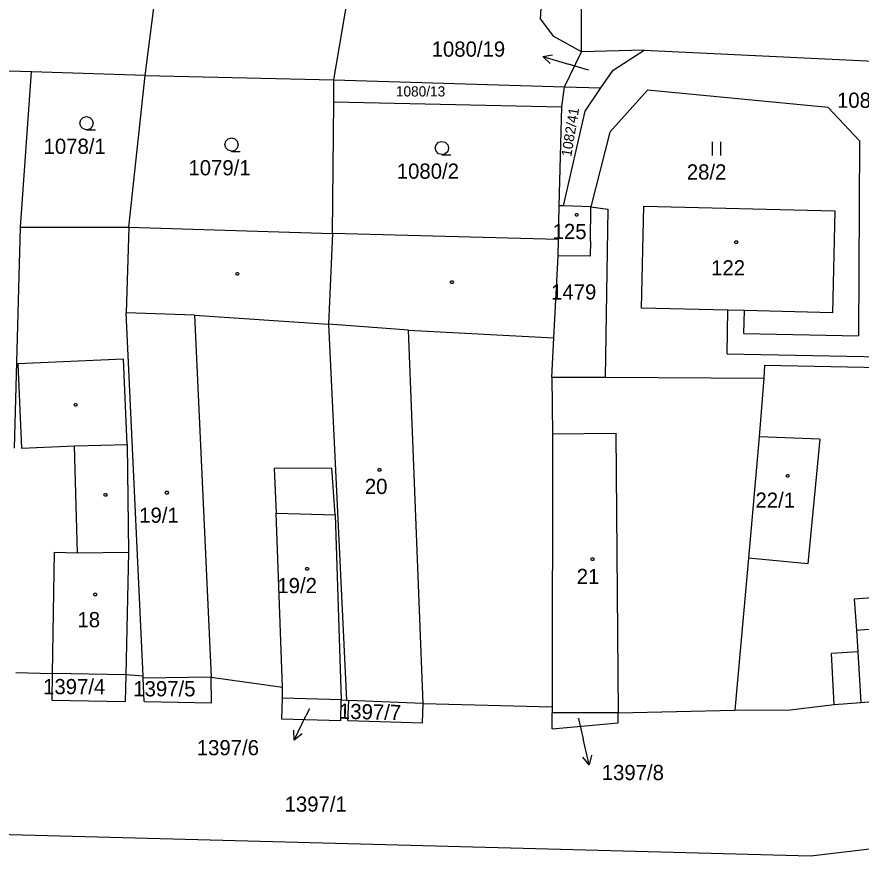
# Model space of a CAD drawing. Extents: x -852001 to -842497, y -1063614 to -1052182.
# Drawn here: x -849494.9 to -849400.5, y -1056341.3 to -1056247.4 of the extents above; entities that cross this region are included whole.
import ezdxf

# ---------------------------------------------------------------- set-up
doc = ezdxf.new("R2010")
doc.units = 0
for name, color, linetype in [('Default', 7, 'Continuous'), ('KN_HRANICE', 7, 'Continuous'), ('KN_KULTURY', 7, 'Continuous'), ('KN_PARCELY', 7, 'Continuous'), ('KN_SLUCKY', 7, 'Continuous')]:
    doc.layers.add(name, color=color, linetype=linetype)

# ---------------------------------------------------------------- blocks, each defined once
blk = doc.blocks.new('304')
at = {"layer": 'Default'}
blk.add_lwpolyline([(0, 0), (-0.38, 0.1), (-0.65, 0.37), (-0.75, 0.74), (-0.65, 1.11), (-0.38, 1.38), (-0.01, 1.48), (0.36, 1.38), (0.63, 1.11), (0.73, 0.73), (0.63, 0.35), (0.36, 0.08), (-0.02, -0.02), (0.98, -0.02)], dxfattribs=at)
blk = doc.blocks.new('306')
at = {"layer": 'Default'}
for p, q in [((-0.5, 1.5), (-0.5, 0)), ((0.5, 0), (0.5, 1.5))]:
    blk.add_line(p, q, dxfattribs=at)
blk = doc.blocks.new('10292')
at = {"layer": 'Default'}
blk.add_line((0, 3), (0, 0), dxfattribs=at)
blk.add_lwpolyline([(-0.5, 2), (0, 3), (0.5, 2)], dxfattribs=at)
blk = doc.blocks.new('402')
at = {"layer": 'Default'}
blk.add_lwpolyline([(0.09, 0.15), (0.18, 0), (0.09, -0.15), (-0.09, -0.15), (-0.18, 0), (-0.09, 0.15), (0.09, 0.15)], dxfattribs=at)

msp = doc.modelspace()

# ---------------------------------------------------------------- linework, layer by layer
at = {"layer": 'KN_HRANICE'}
for p, q in [((-849436.33, -1056247.63), (-849434.92, -1056222.51)), ((-849436.33, -1056247.63), (-849434.92, -1056222.51)), ((-849459.44, -1056254.46), (-849456.85, -1056239.17)), ((-849459.44, -1056254.46), (-849456.85, -1056239.17)), ((-849480.53, -1056253.97), (-849478.74, -1056239.77)), ((-849480.53, -1056253.97), (-849478.74, -1056239.77)), ((-849431.76, -1056251.31), (-849431.74, -1056242.65)), ((-849431.76, -1056251.31), (-849431.74, -1056242.65)), ((-849434.87, -1056249.61), (-849436.33, -1056247.63)), ((-849434.87, -1056249.61), (-849436.33, -1056247.63)), ((-849431.76, -1056251.31), (-849434.87, -1056249.61)), ((-849431.76, -1056251.31), (-849434.87, -1056249.61)), ((-849433.67, -1056255.23), (-849431.76, -1056251.31)), ((-849433.67, -1056255.23), (-849431.76, -1056251.31)), ((-849424.74, -1056251.13), (-849431.76, -1056251.31)), ((-849424.74, -1056251.13), (-849431.76, -1056251.31)), ((-849428.22, -1056253.36), (-849424.74, -1056251.13)), ((-849428.22, -1056253.36), (-849424.74, -1056251.13)), ((-849424.74, -1056251.13), (-849362.03, -1056254.15)), ((-849424.74, -1056251.13), (-849362.03, -1056254.15)), ((-849493.22, -1056253.57), (-849506.8, -1056253.15)), ((-849493.22, -1056253.57), (-849506.8, -1056253.15)), ((-849494.45, -1056270.95), (-849493.22, -1056253.57)), ((-849494.45, -1056270.95), (-849493.22, -1056253.57)), ((-849480.53, -1056253.97), (-849493.22, -1056253.57)), ((-849480.53, -1056253.97), (-849493.22, -1056253.57)), ((-849482.35, -1056270.93), (-849480.53, -1056253.97)), ((-849482.35, -1056270.93), (-849480.53, -1056253.97)), ((-849480.53, -1056253.97), (-849459.44, -1056254.46)), ((-849480.53, -1056253.97), (-849459.44, -1056254.46)), ((-849429.59, -1056255.35), (-849428.22, -1056253.36)), ((-849429.59, -1056255.35), (-849428.22, -1056253.36)), ((-849459.46, -1056256.93), (-849459.44, -1056254.46)), ((-849459.46, -1056256.93), (-849459.44, -1056254.46)), ((-849459.44, -1056254.46), (-849433.67, -1056255.23)), ((-849459.44, -1056254.46), (-849433.67, -1056255.23)), ((-849433.96, -1056257.48), (-849433.67, -1056255.23)), ((-849433.96, -1056257.48), (-849433.67, -1056255.23)), ((-849433.67, -1056255.23), (-849429.59, -1056255.35)), ((-849433.67, -1056255.23), (-849429.59, -1056255.35)), ((-849431.37, -1056257.95), (-849429.59, -1056255.35)), ((-849431.37, -1056257.95), (-849429.59, -1056255.35)), ((-849424.4, -1056255.6), (-849428.61, -1056260.33)), ((-849424.4, -1056255.6), (-849428.61, -1056260.33)), ((-849404.18, -1056257.55), (-849424.4, -1056255.6)), ((-849404.18, -1056257.55), (-849424.4, -1056255.6)), ((-849459.61, -1056271.66), (-849459.46, -1056256.93)), ((-849459.61, -1056271.66), (-849459.46, -1056256.93)), ((-849459.46, -1056256.93), (-849433.96, -1056257.48)), ((-849459.46, -1056256.93), (-849433.96, -1056257.48)), ((-849434.27, -1056268.55), (-849433.96, -1056257.48)), ((-849434.27, -1056268.55), (-849433.96, -1056257.48)), ((-849433.77, -1056268.56), (-849431.37, -1056257.95)), ((-849433.77, -1056268.56), (-849431.37, -1056257.95)), ((-849400.7, -1056261.28), (-849404.18, -1056257.55)), ((-849400.7, -1056261.28), (-849404.18, -1056257.55)), ((-849428.61, -1056260.33), (-849430.72, -1056268.66)), ((-849428.61, -1056260.33), (-849430.72, -1056268.66)), ((-849400.7, -1056261.28), (-849400.81, -1056283.1)), ((-849400.7, -1056261.28), (-849400.81, -1056283.1)), ((-849434.34, -1056272.32), (-849434.27, -1056268.55)), ((-849434.34, -1056272.32), (-849434.27, -1056268.55)), ((-849433.77, -1056268.56), (-849434.27, -1056268.55)), ((-849433.77, -1056268.56), (-849434.27, -1056268.55)), ((-849430.72, -1056268.66), (-849433.77, -1056268.56)), ((-849430.72, -1056268.66), (-849433.77, -1056268.56)), ((-849430.76, -1056272.49), (-849430.72, -1056268.66)), ((-849430.76, -1056272.49), (-849430.72, -1056268.66)), ((-849430.72, -1056268.66), (-849428.8, -1056268.93)), ((-849430.72, -1056268.66), (-849428.8, -1056268.93)), ((-849428.8, -1056268.93), (-849429.11, -1056287.73)), ((-849428.8, -1056268.93), (-849429.11, -1056287.73)), ((-849425.04, -1056279.98), (-849424.78, -1056268.57)), ((-849425.04, -1056279.98), (-849424.78, -1056268.57)), ((-849424.78, -1056268.57), (-849403.43, -1056269.1)), ((-849424.78, -1056268.57), (-849403.43, -1056269.1)), ((-849403.43, -1056269.1), (-849403.71, -1056280.52)), ((-849403.43, -1056269.1), (-849403.71, -1056280.52)), ((-849495.12, -1056295.64), (-849494.45, -1056270.95)), ((-849495.12, -1056295.64), (-849494.45, -1056270.95)), ((-849494.45, -1056270.95), (-849482.35, -1056270.93)), ((-849494.45, -1056270.95), (-849482.35, -1056270.93)), ((-849482.35, -1056270.93), (-849482.67, -1056280.51)), ((-849482.35, -1056270.93), (-849482.67, -1056280.51)), ((-849482.35, -1056270.93), (-849459.61, -1056271.66)), ((-849482.35, -1056270.93), (-849459.61, -1056271.66)), ((-849459.61, -1056271.66), (-849460.03, -1056281.78)), ((-849459.61, -1056271.66), (-849460.03, -1056281.78)), ((-849434.34, -1056272.32), (-849459.61, -1056271.66)), ((-849434.34, -1056272.32), (-849459.61, -1056271.66)), ((-849434.38, -1056274.15), (-849434.34, -1056272.32)), ((-849434.38, -1056274.15), (-849434.34, -1056272.32)), ((-849430.76, -1056272.49), (-849430.78, -1056274.18)), ((-849430.76, -1056272.49), (-849430.78, -1056274.18)), ((-849434.84, -1056283.32), (-849434.38, -1056274.15)), ((-849434.84, -1056283.32), (-849434.38, -1056274.15)), ((-849430.78, -1056274.18), (-849434.38, -1056274.15)), ((-849430.78, -1056274.18), (-849434.38, -1056274.15)), ((-849480.75, -1056321.14), (-849482.67, -1056280.51)), ((-849480.75, -1056321.14), (-849482.67, -1056280.51)), ((-849415.41, -1056280.22), (-849425.04, -1056279.98)), ((-849415.41, -1056280.22), (-849425.04, -1056279.98)), ((-849415.48, -1056285.11), (-849415.41, -1056280.22)), ((-849415.48, -1056285.11), (-849415.41, -1056280.22)), ((-849413.55, -1056280.27), (-849415.41, -1056280.22)), ((-849413.55, -1056280.27), (-849415.41, -1056280.22)), ((-849413.61, -1056282.82), (-849413.55, -1056280.27)), ((-849413.61, -1056282.82), (-849413.55, -1056280.27)), ((-849403.71, -1056280.52), (-849413.55, -1056280.27)), ((-849403.71, -1056280.52), (-849413.55, -1056280.27)), ((-849460.03, -1056281.78), (-849458.02, -1056323.85)), ((-849460.03, -1056281.78), (-849458.02, -1056323.85)), ((-849435.06, -1056287.7), (-849434.84, -1056283.32)), ((-849435.06, -1056287.7), (-849434.84, -1056283.32)), ((-849413.61, -1056282.82), (-849400.81, -1056283.1)), ((-849413.61, -1056282.82), (-849400.81, -1056283.1)), ((-849415.48, -1056285.11), (-849362.36, -1056286.11)), ((-849415.48, -1056285.11), (-849362.36, -1056286.11)), ((-849411.31, -1056286.39), (-849411.38, -1056287.83)), ((-849411.31, -1056286.39), (-849411.38, -1056287.83)), ((-849389.17, -1056286.88), (-849411.31, -1056286.39)), ((-849389.17, -1056286.88), (-849411.31, -1056286.39)), ((-849435.06, -1056287.7), (-849434.99, -1056294.05)), ((-849435.06, -1056287.7), (-849429.11, -1056287.73)), ((-849435.06, -1056287.7), (-849434.99, -1056294.05)), ((-849435.06, -1056287.7), (-849429.11, -1056287.73)), ((-849429.11, -1056287.73), (-849411.38, -1056287.83)), ((-849429.11, -1056287.73), (-849411.38, -1056287.83)), ((-849411.38, -1056287.83), (-849411.89, -1056294.39)), ((-849411.38, -1056287.83), (-849411.89, -1056294.39)), ((-849434.99, -1056294.05), (-849435.03, -1056324.6)), ((-849434.99, -1056294.05), (-849435.03, -1056324.6)), ((-849411.89, -1056294.39), (-849413.11, -1056307.95)), ((-849411.89, -1056294.39), (-849413.11, -1056307.95)), ((-849459.67, -1056297.88), (-849466.12, -1056297.93)), ((-849459.67, -1056297.88), (-849466.12, -1056297.93)), ((-849466.12, -1056297.93), (-849465.89, -1056302.94)), ((-849466.12, -1056297.93), (-849465.89, -1056302.94)), ((-849459.31, -1056303.12), (-849459.67, -1056297.88)), ((-849459.31, -1056303.12), (-849459.67, -1056297.88)), ((-849465.19, -1056322.38), (-849465.89, -1056302.94)), ((-849465.19, -1056322.38), (-849465.89, -1056302.94)), ((-849459.31, -1056303.12), (-849458.61, -1056323.81)), ((-849459.31, -1056303.12), (-849458.61, -1056323.81)), ((-849413.11, -1056307.95), (-849414.63, -1056324.97)), ((-849413.11, -1056307.95), (-849414.63, -1056324.97)), ((-849394.9, -1056312.07), (-849401.27, -1056312.56)), ((-849394.9, -1056312.07), (-849401.27, -1056312.56)), ((-849401.27, -1056312.56), (-849401.01, -1056315.99)), ((-849401.27, -1056312.56), (-849401.01, -1056315.99)), ((-849401.01, -1056315.99), (-849400.86, -1056318.43)), ((-849401.01, -1056315.99), (-849400.86, -1056318.43)), ((-849400.86, -1056318.43), (-849403.83, -1056318.61)), ((-849400.86, -1056318.43), (-849403.83, -1056318.61)), ((-849403.52, -1056324.31), (-849403.83, -1056318.61)), ((-849403.52, -1056324.31), (-849403.83, -1056318.61)), ((-849494.97, -1056320.74), (-849490.92, -1056320.87)), ((-849494.97, -1056320.74), (-849490.92, -1056320.87)), ((-849490.92, -1056320.87), (-849490.97, -1056323.82)), ((-849490.92, -1056320.87), (-849490.97, -1056323.82)), ((-849482.68, -1056320.99), (-849490.92, -1056320.87)), ((-849482.68, -1056320.99), (-849490.92, -1056320.87)), ((-849482.68, -1056320.99), (-849482.75, -1056323.99)), ((-849482.68, -1056320.99), (-849482.75, -1056323.99)), ((-849480.75, -1056321.14), (-849482.68, -1056320.99)), ((-849480.75, -1056321.14), (-849482.68, -1056320.99)), ((-849480.74, -1056321.39), (-849480.75, -1056321.14)), ((-849480.74, -1056321.39), (-849480.75, -1056321.14)), ((-849473.17, -1056321.25), (-849480.74, -1056321.39)), ((-849473.17, -1056321.25), (-849480.74, -1056321.39)), ((-849473.12, -1056324.15), (-849473.17, -1056321.25)), ((-849473.17, -1056321.25), (-849465.19, -1056322.38)), ((-849473.12, -1056324.15), (-849473.17, -1056321.25)), ((-849473.17, -1056321.25), (-849465.19, -1056322.38)), ((-849480.64, -1056323.99), (-849480.74, -1056321.39)), ((-849480.64, -1056323.99), (-849480.74, -1056321.39)), ((-849465.18, -1056323.63), (-849465.19, -1056322.38)), ((-849465.18, -1056323.63), (-849465.19, -1056322.38)), ((-849490.97, -1056323.82), (-849482.75, -1056323.99)), ((-849490.97, -1056323.82), (-849482.75, -1056323.99)), ((-849480.64, -1056323.99), (-849473.12, -1056324.15)), ((-849480.64, -1056323.99), (-849473.12, -1056324.15)), ((-849465.24, -1056325.98), (-849465.18, -1056323.63)), ((-849465.24, -1056325.98), (-849465.18, -1056323.63)), ((-849458.61, -1056323.81), (-849465.18, -1056323.63)), ((-849458.61, -1056323.81), (-849465.18, -1056323.63)), ((-849458.67, -1056326.16), (-849458.61, -1056323.81)), ((-849458.67, -1056326.16), (-849458.61, -1056323.81)), ((-849458.61, -1056323.81), (-849458.02, -1056323.85)), ((-849458.61, -1056323.81), (-849458.02, -1056323.85)), ((-849458.02, -1056323.85), (-849457.77, -1056323.86)), ((-849458.02, -1056323.85), (-849457.77, -1056323.86)), ((-849457.87, -1056326.11), (-849457.77, -1056323.86)), ((-849457.87, -1056326.11), (-849457.77, -1056323.86)), ((-849449.46, -1056324.22), (-849457.77, -1056323.86)), ((-849449.46, -1056324.22), (-849457.77, -1056323.86)), ((-849403.52, -1056324.31), (-849400.53, -1056324.08)), ((-849403.52, -1056324.31), (-849400.53, -1056324.08)), ((-849400.53, -1056324.08), (-849392.34, -1056323.46)), ((-849400.53, -1056324.08), (-849392.34, -1056323.46)), ((-849449.55, -1056326.37), (-849449.46, -1056324.22)), ((-849449.55, -1056326.37), (-849449.46, -1056324.22)), ((-849449.46, -1056324.22), (-849435.03, -1056324.6)), ((-849449.46, -1056324.22), (-849435.03, -1056324.6)), ((-849435.03, -1056324.6), (-849435.03, -1056325.25)), ((-849435.03, -1056324.6), (-849435.03, -1056325.25)), ((-849427.65, -1056325.24), (-849414.63, -1056324.97)), ((-849427.65, -1056325.24), (-849414.63, -1056324.97)), ((-849414.63, -1056324.97), (-849408.44, -1056324.93)), ((-849414.63, -1056324.97), (-849408.44, -1056324.93)), ((-849408.44, -1056324.93), (-849403.52, -1056324.31)), ((-849408.44, -1056324.93), (-849403.52, -1056324.31)), ((-849458.67, -1056326.16), (-849465.24, -1056325.98)), ((-849458.67, -1056326.16), (-849465.24, -1056325.98)), ((-849427.65, -1056325.24), (-849435.03, -1056325.25)), ((-849427.65, -1056325.24), (-849435.03, -1056325.25)), ((-849435.03, -1056327.05), (-849435.03, -1056325.25)), ((-849435.03, -1056327.05), (-849435.03, -1056325.25)), ((-849427.65, -1056326.39), (-849427.65, -1056325.24)), ((-849427.65, -1056326.39), (-849427.65, -1056325.24)), ((-849457.87, -1056326.11), (-849449.55, -1056326.37)), ((-849457.87, -1056326.11), (-849449.55, -1056326.37)), ((-849435.03, -1056327.05), (-849427.65, -1056326.39)), ((-849435.03, -1056327.05), (-849427.65, -1056326.39)), ((-849406.11, -1056341.28), (-849532.06, -1056337.93)), ((-849406.11, -1056341.28), (-849532.06, -1056337.93)), ((-849396.03, -1056340.06), (-849406.11, -1056341.28)), ((-849396.03, -1056340.06), (-849406.11, -1056341.28))]:
    msp.add_line(p, q, dxfattribs=at)
at = {"layer": 'KN_PARCELY'}
for p, q in [((-849430.97, -1056253.37), (-849433.22, -1056252.71)), ((-849430.97, -1056253.37), (-849433.22, -1056252.71)), ((-849462.18, -1056324.8), (-849462.57, -1056325.6)), ((-849462.18, -1056324.8), (-849462.57, -1056325.6)), ((-849432.09, -1056325.94), (-849431.57, -1056328.16)), ((-849432.09, -1056325.94), (-849431.57, -1056328.16))]:
    msp.add_line(p, q, dxfattribs=at)
at = {"layer": 'KN_SLUCKY'}
for p, q in [((-849475.02, -1056280.76), (-849482.67, -1056280.51)), ((-849475.02, -1056280.76), (-849482.67, -1056280.51)), ((-849475.02, -1056280.76), (-849460.03, -1056281.78)), ((-849475.02, -1056280.76), (-849473.17, -1056321.25)), ((-849475.02, -1056280.76), (-849460.03, -1056281.78)), ((-849475.02, -1056280.76), (-849473.17, -1056321.25)), ((-849451.09, -1056282.46), (-849460.03, -1056281.78)), ((-849451.09, -1056282.46), (-849460.03, -1056281.78)), ((-849449.46, -1056324.22), (-849451.09, -1056282.46)), ((-849451.09, -1056282.46), (-849434.84, -1056283.32)), ((-849449.46, -1056324.22), (-849451.09, -1056282.46)), ((-849451.09, -1056282.46), (-849434.84, -1056283.32)), ((-849482.97, -1056285.71), (-849494.77, -1056286.24)), ((-849482.97, -1056285.71), (-849494.77, -1056286.24)), ((-849494.77, -1056286.24), (-849494.34, -1056295.65)), ((-849494.77, -1056286.24), (-849494.34, -1056295.65)), ((-849482.56, -1056295.24), (-849482.97, -1056285.71)), ((-849482.56, -1056295.24), (-849482.97, -1056285.71)), ((-849434.99, -1056294.05), (-849427.93, -1056293.99)), ((-849434.99, -1056294.05), (-849427.93, -1056293.99)), ((-849427.93, -1056293.99), (-849427.65, -1056325.24)), ((-849427.93, -1056293.99), (-849427.65, -1056325.24)), ((-849405.13, -1056294.64), (-849411.89, -1056294.39)), ((-849405.13, -1056294.64), (-849411.89, -1056294.39)), ((-849405.13, -1056294.64), (-849406.45, -1056308.58)), ((-849405.13, -1056294.64), (-849406.45, -1056308.58)), ((-849494.34, -1056295.65), (-849488.42, -1056295.39)), ((-849494.34, -1056295.65), (-849488.42, -1056295.39)), ((-849488.42, -1056295.39), (-849482.56, -1056295.24)), ((-849488.42, -1056295.39), (-849482.56, -1056295.24)), ((-849488.1, -1056307.35), (-849488.42, -1056295.39)), ((-849488.1, -1056307.35), (-849488.42, -1056295.39)), ((-849482.56, -1056295.24), (-849482.38, -1056307.29)), ((-849482.56, -1056295.24), (-849482.38, -1056307.29)), ((-849465.89, -1056302.94), (-849459.31, -1056303.12)), ((-849465.89, -1056302.94), (-849459.31, -1056303.12)), ((-849490.71, -1056307.29), (-849490.92, -1056320.87)), ((-849490.71, -1056307.29), (-849490.92, -1056320.87)), ((-849490.71, -1056307.29), (-849488.1, -1056307.35)), ((-849490.71, -1056307.29), (-849488.1, -1056307.35)), ((-849488.1, -1056307.35), (-849482.38, -1056307.29)), ((-849488.1, -1056307.35), (-849482.38, -1056307.29)), ((-849482.38, -1056307.29), (-849482.68, -1056320.99)), ((-849482.38, -1056307.29), (-849482.68, -1056320.99)), ((-849406.45, -1056308.58), (-849413.11, -1056307.95)), ((-849406.45, -1056308.58), (-849413.11, -1056307.95)), ((-849401.01, -1056315.99), (-849394.64, -1056315.5)), ((-849401.01, -1056315.99), (-849394.64, -1056315.5)), ((-849400.86, -1056318.43), (-849400.53, -1056324.08)), ((-849400.86, -1056318.43), (-849400.53, -1056324.08))]:
    msp.add_line(p, q, dxfattribs=at)

# ---------------------------------------------------------------- block references
at = {"layer": 'KN_KULTURY'}
for name, p in [('304', (-849487.07, -1056260.04)), ('304', (-849487.07, -1056260.04)), ('304', (-849470.88, -1056262.44)), ('304', (-849470.88, -1056262.44)), ('304', (-849447.35, -1056262.82)), ('304', (-849447.35, -1056262.82)), ('306', (-849416.67, -1056262.91)), ('306', (-849416.67, -1056262.91)), ('402', (-849432.3, -1056269.56)), ('402', (-849432.3, -1056269.56)), ('402', (-849414.48, -1056272.63)), ('402', (-849414.48, -1056272.63)), ('402', (-849470.23, -1056276.14)), ('402', (-849470.23, -1056276.14)), ('402', (-849446.26, -1056277.09)), ('402', (-849446.26, -1056277.09)), ('402', (-849488.3, -1056290.81)), ('402', (-849488.3, -1056290.81)), ('402', (-849454.34, -1056298.09)), ('402', (-849454.34, -1056298.09)), ('402', (-849408.72, -1056298.76)), ('402', (-849408.72, -1056298.76)), ('402', (-849478.12, -1056300.63)), ('402', (-849478.12, -1056300.63)), ('402', (-849484.97, -1056300.89)), ('402', (-849484.97, -1056300.89)), ('402', (-849430.54, -1056308.07)), ('402', (-849430.54, -1056308.07)), ('402', (-849462.42, -1056309.16)), ('402', (-849462.42, -1056309.16)), ('402', (-849486.13, -1056312.03)), ('402', (-849486.13, -1056312.03))]:
    msp.add_blockref(name, p, dxfattribs=at)
at = {"layer": 'KN_PARCELY'}
for p, rotation in [((-849433.22, -1056252.71), 73.682372), ((-849433.22, -1056252.71), 73.682372), ((-849462.57, -1056325.6), 153.95376000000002), ((-849462.57, -1056325.6), 153.95376000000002), ((-849431.57, -1056328.16), -166.85592700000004), ((-849431.57, -1056328.16), -166.85592700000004)]:
    msp.add_blockref('10292', p, dxfattribs=dict(at, rotation=rotation))

# ---------------------------------------------------------------- texts
for s, height, p in [('1080/19', 1.7, (-849448.511, -1056251.87)), ('1080/19', 1.7, (-849448.511, -1056251.87)), ('1080/19', 0.1, (-849431.313, -1056253.37)), ('1080/19', 0.1, (-849431.313, -1056253.37)), ('1080/13', 1.14, (-849452.506, -1056256.32)), ('1080/13', 1.14, (-849452.506, -1056256.32)), ('1082/11', 1.7, (-849403.206, -1056257.59)), ('1082/11', 1.7, (-849403.206, -1056257.59)), ('1078/1', 1.7, (-849491.887, -1056262.74)), ('1078/1', 1.7, (-849491.887, -1056262.74)), ('1079/1', 1.7, (-849475.697, -1056265.14)), ('1079/1', 1.7, (-849475.697, -1056265.14)), ('1080/2', 1.7, (-849452.41, -1056265.52)), ('1080/2', 1.7, (-849452.41, -1056265.52)), ('28/2', 1.7, (-849419.989, -1056265.61)), ('28/2', 1.7, (-849419.989, -1056265.61)), ('125', 1.7, (-849434.99, -1056272.27)), ('125', 1.7, (-849434.99, -1056272.27)), ('122', 1.7, (-849417.27, -1056276.33)), ('122', 1.7, (-849417.27, -1056276.33)), ('1479', 1.7, (-849435.159, -1056279.03)), ('1479', 1.7, (-849435.159, -1056279.03)), ('20', 1.7, (-849455.979, -1056300.78)), ('20', 1.7, (-849455.979, -1056300.78)), ('22/1', 1.7, (-849412.316, -1056302.32)), ('22/1', 1.7, (-849412.316, -1056302.32)), ('19/1', 1.7, (-849481.198, -1056304)), ('19/1', 1.7, (-849481.198, -1056304)), ('21', 1.7, (-849432.296, -1056310.85)), ('21', 1.7, (-849432.296, -1056310.85)), ('19/2', 1.7, (-849465.76, -1056311.87)), ('19/2', 1.7, (-849465.76, -1056311.87)), ('18', 1.7, (-849488.1, -1056315.68)), ('18', 1.7, (-849488.1, -1056315.68)), ('1397/4', 1.7, (-849491.94, -1056323.17)), ('1397/4', 1.7, (-849491.94, -1056323.17)), ('1397/5', 1.7, (-849481.86, -1056323.41)), ('1397/5', 1.7, (-849481.86, -1056323.41)), ('1397/6', 0.1, (-849462.478, -1056324.8)), ('1397/6', 0.1, (-849462.478, -1056324.8)), ('1397/8', 0.1, (-849432.388, -1056325.94)), ('1397/8', 0.1, (-849432.388, -1056325.94)), ('1397/6', 1.7, (-849474.763, -1056330)), ('1397/6', 1.7, (-849474.763, -1056330)), ('1397/8', 1.7, (-849429.5, -1056332.78)), ('1397/8', 1.7, (-849429.5, -1056332.78)), ('1397/1', 1.7, (-849464.947, -1056336.31)), ('1397/1', 1.7, (-849464.947, -1056336.31))]:
    msp.add_text(s, height=height, dxfattribs=at).set_placement(p)
for s, height, rotation, p in [('1082/41', 1.14, 80.73, (-849432.908, -1056263.114)), ('1082/41', 1.14, 80.73, (-849432.908, -1056263.114)), ('1397/7', 1.7, 358.614, (-849458.888, -1056325.908)), ('1397/7', 1.7, 358.614, (-849458.888, -1056325.908))]:
    msp.add_text(s, height=height, rotation=rotation, dxfattribs=at).set_placement(p)

doc.saveas('drawing.dxf')
